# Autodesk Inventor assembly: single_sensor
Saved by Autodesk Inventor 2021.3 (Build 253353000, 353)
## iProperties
Created: 2023-09
Part Number: single_sensor
Document SubType Name: Assembly
Designer: AdminForWorker
Title: single_sensor v13
Author: AdminForWorker
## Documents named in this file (3)
- z:\worker\convert-fusion-r04-cosv3\tmp\job-1\76\output\files\2c3f0289-2480-417a-a19e-1f8ca8a1dc70\944db6a7-bc44-4a3e-992f-cb28147857da.iam
- z:\worker\convert-fusion-r04-cosv3\tmp\job-1\76\output\files\2c3f0289-2480-417a-a19e-1f8ca8a1dc70\cover.ipt
- z:\worker\convert-fusion-r04-cosv3\tmp\job-1\76\output\files\2c3f0289-2480-417a-a19e-1f8ca8a1dc70\Part4.ipt
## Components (2 placed, 2 different names)
1. cover:1
2. Part4
